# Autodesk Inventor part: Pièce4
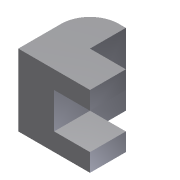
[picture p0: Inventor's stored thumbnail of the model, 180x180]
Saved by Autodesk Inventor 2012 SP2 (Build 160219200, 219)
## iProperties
Created: 2013-10
Part Number: Pièce4
Material: Default
Document SubType Name: Modeling
Designer: papa
Density: 1 g/cm^3
Author: papa
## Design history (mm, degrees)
sketch "Esquisse1"
  geometry: L1 (-10, 10)-(10, 10); L2 (10, 10)-(10, -10); L3 (10, -10)-(-10, -10); L4 (-10, -10)-(-10, 10); L5 (0, 0)-(0, 15.334); L6 (0, 0)-(18.895, 0)
  constraints: 12 end point, 3 parallel, 2 perpendicular, 1 horizontal, 2 other
  dimensions: "d0" = 20 distance of L3.end L1.start; "d1" = 20 distance of L2.end L3.end
extrude "Extrusion1" new body sketch "Esquisse1" distance "d2" = 20; taper "d3" = 0 deg
sketch "Esquisse2"
  geometry: L1 (0, 20)-(0, 0) reference; L2 (0, 20)-(-20, 20) reference; L3 (-20, 20)-(0, 20); L4 (0, 20)-(0, 10); L5 (0, 10)-(-20, 10); L6 (-20, 10)-(-20, 20)
  constraints: 8 end point, 2 parallel, 1 horizontal, 1 perpendicular
extrude "Extrusion2" cut sketch "Esquisse2" distance "d4" = 10; taper "d5" = 0 deg
sketch "Esquisse3"
  geometry: L1 (20, 10)-(0, 10) reference; L2 (0, 10)-(0, 0) reference; L3 (20, 10)-(20, 0) reference; L4 (5, 10)-(15, 10); L5 (15, 10)-(15, -1.738); L6 (15, -1.738)-(5, -1.738); L7 (5, -1.738)-(5, 10)
  constraints: 8 end point, 2 parallel, 1 horizontal, 1 perpendicular, 1 point on line
  dimensions: "d6" = 5 distance between parallel lines of L2 L7; "d7" = 5 distance between parallel lines of L3 L5 (= d6)
extrude "Extrusion3" cut sketch "Esquisse3" distance "d8" = 10; taper "d9" = 0 deg
fillet "Congé1" dims "d10" = 8
node "Solide1"
